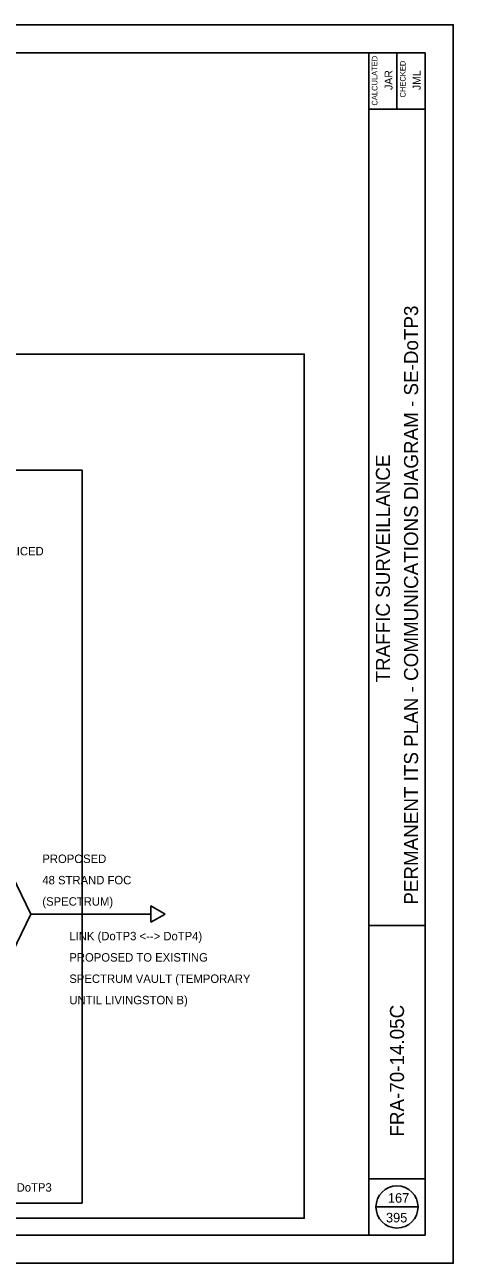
# Model space of a CAD drawing. Extents: x 1805893 to 1833564, y 708898 to 716199.
# Drawn here: x 1832630.8 to 1832783.1, y 714257.9 to 714697.9 of the extents above; entities that cross this region are included whole.
import ezdxf

# ---------------------------------------------------------------- set-up
doc = ezdxf.new("R2010")
doc.units = 0
for name, color, linetype in [('BR_P_Sub_Hidden', 7, 'Continuous'), ('SH_Border', 7, 'Continuous'), ('SH_Cut_Line', 7, 'Continuous'), ('SH_Data', 7, 'Continuous')]:
    doc.layers.add(name, color=color, linetype=linetype)

msp = doc.modelspace()

# ---------------------------------------------------------------- linework, layer by layer
at = {"layer": 'BR_P_Sub_Hidden'}
for points in [[(1832330.89, 714580.93), (1832730.15, 714580.93), (1832730.15, 714273.91), (1832330.89, 714273.91)], [(1832399.8, 714539.7), (1832651.12, 714539.7), (1832651.12, 714279.3), (1832399.8, 714279.3)]]:
    msp.add_lwpolyline(points, close=True, dxfattribs=at)
at = {"layer": 'SH_Border'}
for p, q in [((1832753.13, 714267.91), (1832753.13, 714687.91)), ((1832763.13, 714687.91), (1832763.13, 714667.91)), ((1832753.13, 714667.91), (1832773.13, 714667.91)), ((1832753.13, 714377.91), (1832773.13, 714377.91)), ((1832753.13, 714287.91), (1832773.13, 714287.91))]:
    msp.add_line(p, q, dxfattribs=at)
msp.add_lwpolyline([(1832143.13, 714687.91), (1832773.13, 714687.91), (1832773.13, 714267.91), (1832143.13, 714267.91)], close=True, dxfattribs=at)
at = {"layer": 'SH_Cut_Line'}
msp.add_lwpolyline([(1832103.13, 714257.91), (1832783.13, 714257.91), (1832783.13, 714697.91), (1832103.13, 714697.91)], close=True, dxfattribs=at)
at = {"layer": 'SH_Data'}
for p, q in [((1832675.65, 714379.04), (1832675.65, 714384.84)), ((1832675.65, 714384.84), (1832680.67, 714381.94)), ((1832632.92, 714381.94), (1832675.65, 714381.94)), ((1832680.67, 714381.94), (1832675.65, 714379.04)), ((1832755.63, 714277.91), (1832770.63, 714277.91))]:
    msp.add_line(p, q, dxfattribs=at)
msp.add_lwpolyline([(1832626.32, 714395.68), (1832632.92, 714381.94), (1832626.32, 714368.2)], dxfattribs=at)
msp.add_lwpolyline([(1832626.32, 714395.68), (1832632.92, 714381.94), (1832626.32, 714368.2)], dxfattribs=at)
msp.add_circle((1832763.13, 714277.91), 7.5, dxfattribs=at)

# ---------------------------------------------------------------- texts
for s, height, p in [('CALCULATED', 2, (1832756.18, 714669.2)), ('CHECKED', 2, (1832766.18, 714672.07)), ('JAR', 2.8, (1832761.53, 714674.74)), ('JML', 2.8, (1832771.53, 714674.7)), ('PERMANENT ITS PLAN - COMMUNICATIONS DIAGRAM - SE-DoTP3', 5, (1832770.63, 714385.29)), ('TRAFFIC SURVEILLANCE', 5, (1832760.63, 714464.23)), ('FRA-70-14.05C', 5, (1832765.63, 714302.9))]:
    msp.add_text(s, height=height, rotation=90, dxfattribs=at).set_placement(p)
for s, height, p in [('0 BUFFER TUBES PASSED THROUGH UNSPLICED', 3, (1832540.76, 714509.4)), ('PROPOSED', 3, (1832637.01, 714400.1)), ('48 STRAND FOC', 3, (1832637.01, 714392.52)), ('(SPECTRUM)', 3, (1832637.01, 714384.94)), ('LINK (DoTP3 <--> DoTP4)', 3, (1832646.61, 714372.64)), ('PROPOSED TO EXISTING ', 3, (1832646.61, 714365.07)), ('SPECTRUM VAULT (TEMPORARY', 3, (1832646.61, 714357.49)), ('UNTIL LIVINGSTON B)', 3, (1832646.61, 714349.91)), ('UNDERGROUND SPLICE ENCLOSURE  DoTP3', 3, (1832552.09, 714283.35)), ('167', 3.4, (1832759.91, 714279.41)), ('395', 3.4, (1832759.21, 714272.41))]:
    msp.add_text(s, height=height, dxfattribs=at).set_placement(p)

doc.saveas('drawing.dxf')
